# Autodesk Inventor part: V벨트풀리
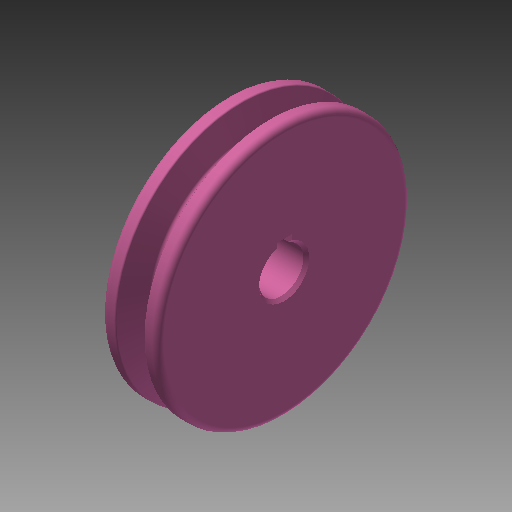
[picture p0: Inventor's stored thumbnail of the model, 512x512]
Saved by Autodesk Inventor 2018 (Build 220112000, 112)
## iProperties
Created: 2018-11
Part Number: V벨트풀리
Material: 알루미늄 6061
Document SubType Name: Modeling
Designer: mduedu
Density: 1 g/cm^3
Appearance: 분홍색
Author: mduedu
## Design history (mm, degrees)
sketch "스케치1"
  geometry: L1 (-9.5, 0)-(9.5, 0); L2 (9.5, 0)-(9.5, 42.7); L3 (9.5, 42.7)-(4.877, 42.7); L4 (-9.5, 42.7)-(-9.5, 0); L5 (-4.877, 42.7)-(-1.953, 33.7); L6 (-1.953, 33.7)-(1.953, 33.7); L7 (1.953, 33.7)-(4.877, 42.7); L8 (0, 0)-(0, 42.7); L9 (-9.5, 40)-(9.5, 40); L10 (-4.877, 42.7)-(-9.5, 42.7); L11 (4.877, 42.7)-(-4.877, 42.7); 3 further points
  constraints: 22 end point, 6 point on line, 4 parallel, 3 perpendicular, 2 midpoint, 1 coincident, 1 horizontal, 1 vertical, 1 other
  dimensions: "d2" = 19 distance of L2.end L4.start; "d3" = 80 diameter of L9 L1; "d4" = 36 deg angle of L7 L5; "d5" = 6.3 distance between parallel lines of L6 L9; "d6" = 8 distance of point (4, 40) point (-4, 40); "d27" = 2.7 distance between parallel lines of L3 L9
revolve "회전1" sketch "스케치1" stored, may be unused: angle "d7" = 90 deg
sketch "스케치2"
  geometry: L1 (-2.5, 7.071)-(2.5, 7.071); L2 (2.5, 7.071)-(2.5, 9.8); L3 (2.5, 9.8)-(-2.5, 9.8); L4 (-2.5, 9.8)-(-2.5, 7.071); A1 r 7.5 centre (0, 0) between (-2.5, 7.071) and (2.5, 7.071); 1 further point
  constraints: 8 end point, 2 parallel, 2 point on circle, 1 centre point, 1 coincident, 1 horizontal, 1 perpendicular
  dimensions: "d8" = 15 diameter of A1; "d10" = 17.3 dimension on A1 L3; "d11" = 5 distance of L2.end L3.end
extrude "돌출1" cut sketch "스케치2" extent not by distance; stored distance "d12" = 10; taper "d13" = 0 deg
chamfer "모따기1" distance "d14" = 1; stored, may be unused: second distance "d15" = 2, angle "d16" = 45 deg
fillet "모깎기1" dims "d17" = 1, "d18" = 0.5, "d19" = 2
sketch "스케치3"
  geometry: C1 r 17.5 at (0, 0); C2 r 28.5 at (0, 0); 1 further point
  constraints: 2 centre point, 2 coincident
  dimensions: "d20" = 35 diameter of C1; "d23" = 57 diameter of C2
extrude "돌출2" cut sketch "스케치3" distance "d24" = 9.5; taper "d25" = 0 deg
fillet "모깎기2" dims "d26" = 3
chamfer "모따기2" distance "d28" = 0.5; stored, may be unused: second distance "d29" = 2, angle "d30" = 45 deg
node "솔리드1"
